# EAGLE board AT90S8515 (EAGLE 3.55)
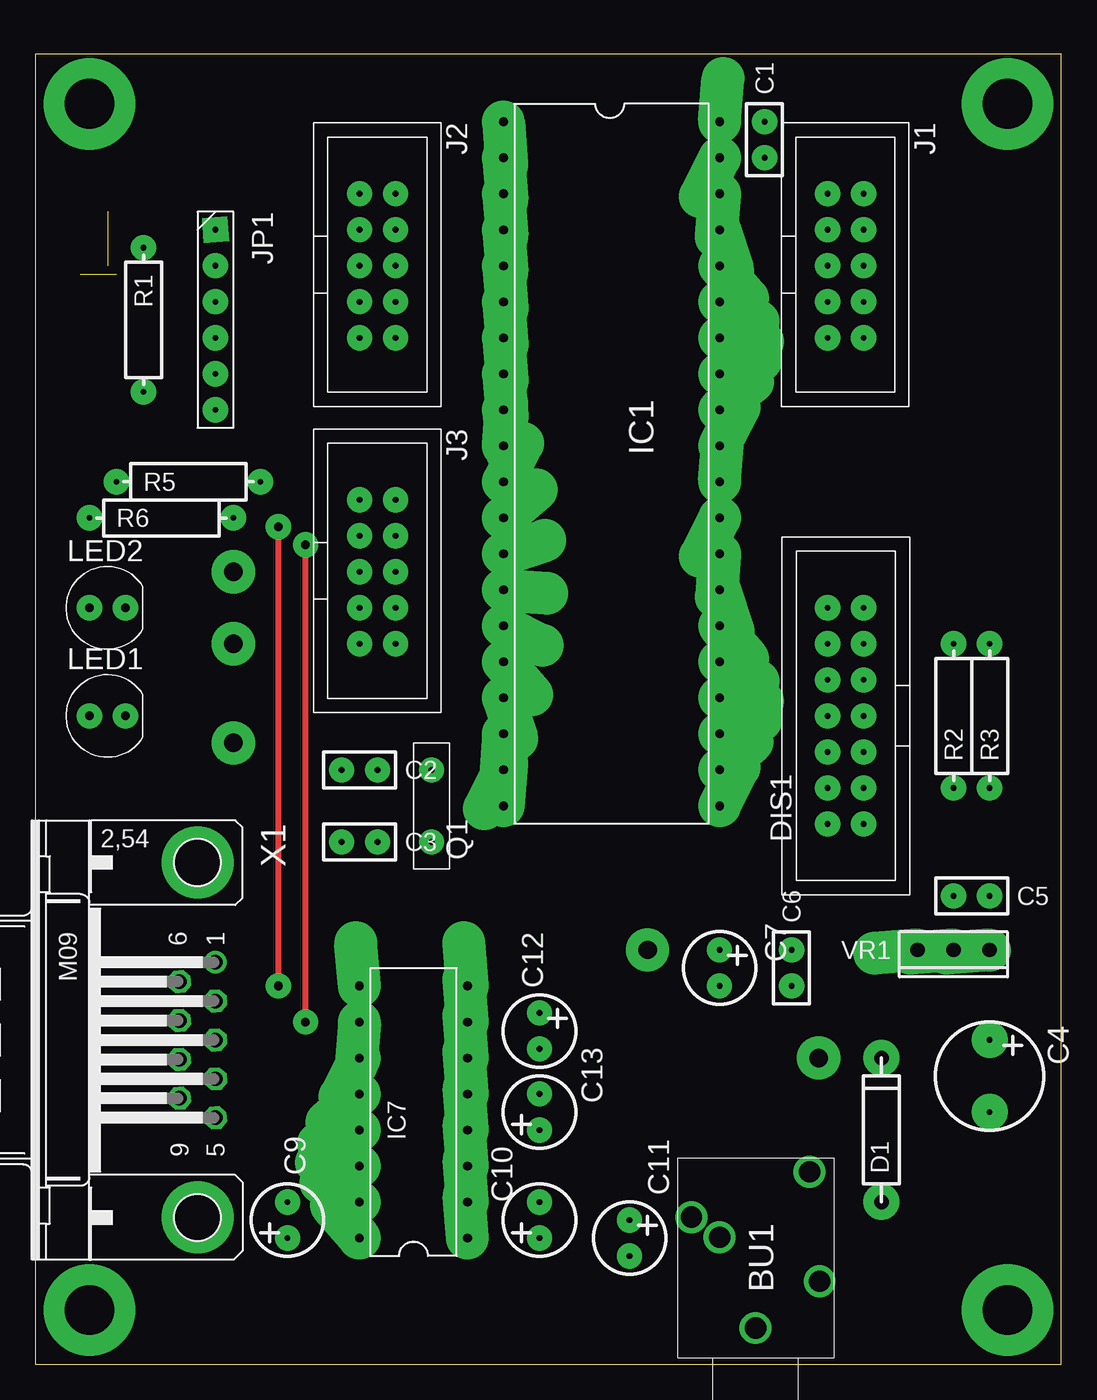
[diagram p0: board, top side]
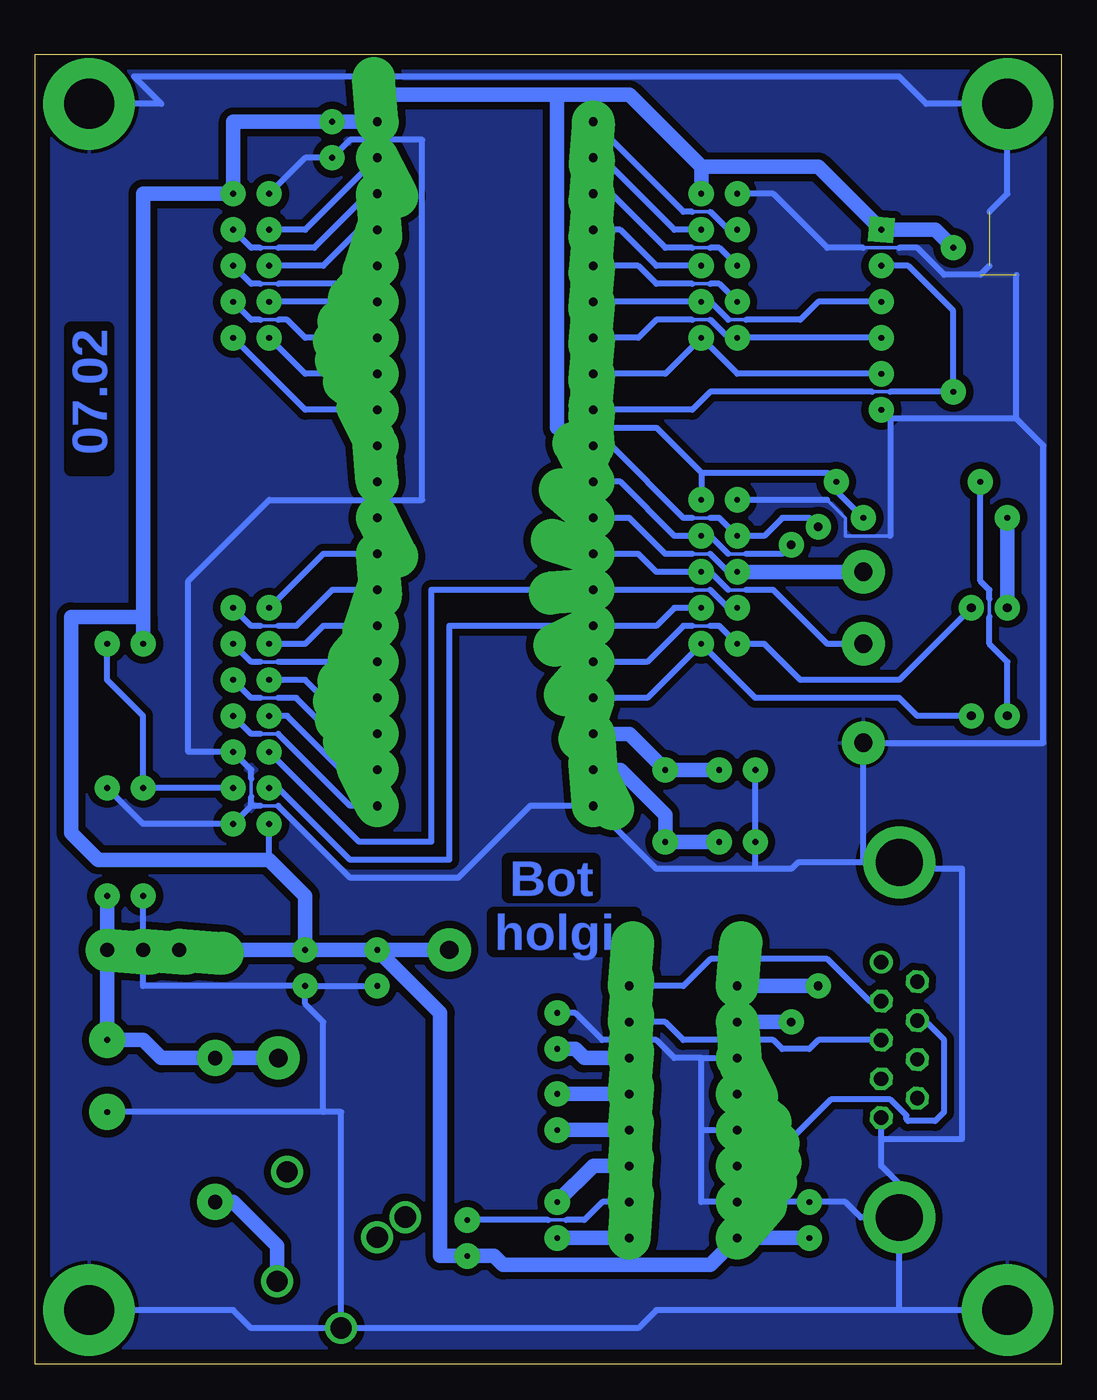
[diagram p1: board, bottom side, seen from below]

Size 72.37 x 92.38 mm. Coordinates in mm from the lower left corner, seen from the top.
Outline: 0,0 72.37,0 72.37,92.38 0,92.38 0,0
Copper layers used: Top, Bottom

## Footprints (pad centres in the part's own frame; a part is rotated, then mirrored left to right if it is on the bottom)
_3,5MM = drill 1.499 pad 2.184 round:  0,0;  3.302,-4.521;  7.823,4.521;  6.401,2.54;  11.024,-3.81
RM2,5 = drill 0.406 pad 1.778 round:  -1.27,0;  1.27,0
KO02 = drill 0.406 pad 2.54 round:  -2.54,0;  2.54,0
KO01 = drill 0.406 pad 1.778 round:  -1.27,0;  1.27,0
O_1A = drill 1.016 pad 2.54 round:  -5.08,0;  5.08,0
7 = drill 0.406 pad 1.778 round:  0,0;  2.54,0;  5.08,0;  7.62,0;  10.16,0;  10.16,2.54;  7.62,2.54;  5.08,2.54;  2.54,2.54;  0,2.54;  12.7,0;  12.7,2.54;  15.24,0;  15.24,2.54
L-40B = drill 0.61 pad 3.048 offset:  -24.13,-7.62;  -21.59,-7.62;  -8.89,-7.62;  -6.35,-7.62;  -19.05,-7.62;  -16.51,-7.62;  -11.43,-7.62;  -13.97,-7.62;  -3.81,-7.62;  -1.27,-7.62;  1.27,-7.62;  3.81,-7.62;  6.35,-7.62;  8.89,-7.62;  11.43,-7.62;  13.97,-7.62;  16.51,-7.62;  19.05,-7.62;  21.59,-7.62;  24.13,-7.62;  24.13,7.62;  21.59,7.62;  19.05,7.62;  16.51,7.62;  13.97,7.62;  11.43,7.62;  8.89,7.62;  6.35,7.62;  3.81,7.62;  1.27,7.62;  -1.27,7.62;  -3.81,7.62;  -6.35,7.62;  -8.89,7.62;  -11.43,7.62;  -13.97,7.62;  -16.51,7.62;  -19.05,7.62;  -21.59,7.62;  -24.13,7.62
L-16B = drill 0.61 pad 3.048 offset:  -8.89,-3.81;  -6.35,-3.81;  6.35,-3.81;  8.89,-3.81;  -3.81,-3.81;  -1.27,-3.81;  3.81,-3.81;  1.27,-3.81;  8.89,3.81;  6.35,3.81;  3.81,3.81;  1.27,3.81;  -1.27,3.81;  -3.81,3.81;  -6.35,3.81;  -8.89,3.81
5 = drill 0.406 pad 1.778 round:  0,0;  2.54,0;  5.08,0;  7.62,0;  10.16,0;  10.16,2.54;  7.62,2.54;  5.08,2.54;  2.54,2.54;  0,2.54
6 = drill 0.406 pad 1.778 square:  0,0 | drill 0.406 pad 1.778 round:  5.08,0;  10.16,0;  12.7,0;  7.62,0;  2.54,0
D_5MM = drill 0.61 pad 1.778 round:  -1.27,0;  1.27,0
GEL = drill 1.295 pad 3.048 round:  0,0
ARZ_ST = drill 0.406 pad 1.778 round:  -2.54,0;  2.54,0
S04 = drill 0.406 pad 1.778 round:  -5.08,0;  5.08,0
HRUNG = drill 3.505 pad 6.452 round:  0,0
220A = drill 1.016 pad 3.048 offset:  -2.54,0;  0,0;  2.54,0
9HP = drill 1.016 pad 1.6 octagon:  5.486,1.27;  2.743,1.27;  0,1.27;  -2.743,1.27;  4.115,-1.27;  1.372,-1.27;  -1.372,-1.27;  -4.115,-1.27 | drill 1.016 pad 1.6 round:  -5.486,1.27 | drill 3.302 pad 5.08 round:  -12.522,0;  12.522,0

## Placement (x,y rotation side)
BU1  BU_3,5MM  [_3,5MM]  50.8,2.54 90 top
C1  C100NK  [RM2,5]  51.44,86.36 90 top
C2  22p  [RM2,5]  22.86,41.91 0 top
C3  22p  [RM2,5]  22.86,36.83 0 top
C4  470u/25  [KO02]  67.31,20.32 270 top
C5  C100NK  [RM2,5]  66.04,33.02 0 top
C6  C100NK  [RM2,5]  53.34,27.94 90 top
C7  100u  [KO01]  48.26,27.94 270 top
C9  10u  [KO01]  17.78,10.16 90 top
C10  10u  [KO01]  35.56,10.16 90 top
C11  10u  [KO01]  41.91,8.89 270 top
C12  10u  [KO01]  35.56,23.5 270 top
C13  10u  [KO01]  35.56,17.78 90 top
D1  1N4001  [O_1A]  59.69,16.51 90 top
DIS1  LCD1  [7]  58.42,38.1 90 top
IC1  90S8515-P  [L-40B]  40.64,63.5 270 top
IC7  MAX232  [L-16B]  26.67,17.78 90 top
J1  8BITPORT  [5]  55.88,82.55 270 top
J2  8BITPORT  [5]  22.86,82.55 270 top
J3  8BITPORT  [5]  22.86,60.96 270 top
JP1  PINHD-1X6  [6]  12.7,80.01 270 top
LED1  rot  [D_5MM]  5.08,45.72 0 top
LED2  grn  [D_5MM]  5.08,53.34 0 top
N1  Int1  [GEL]  13.97,50.8 0 top
N2  Int0  [GEL]  13.97,55.88 0 top
N3  gnd  [GEL]  13.97,43.81 0 top
N4  +5V  [GEL]  43.18,29.21 0 top
N5  +Ub  [GEL]  55.24,21.59 0 top
Q1  8MHz  [ARZ_ST]  27.94,39.37 90 top
R1  100k  [S04]  7.62,73.66 270 top
R2  12k  [S04]  64.77,45.72 90 top
R3  1k  [S04]  67.31,45.72 90 top
R5  1k  [S04]  10.79,62.23 0 top
R6  1k  [S04]  8.89,59.69 0 top
U$30  BOHRUNG  [HRUNG]  3.81,88.9 0 top
U$31  BOHRUNG  [HRUNG]  68.58,88.9 0 top
U$32  BOHRUNG  [HRUNG]  68.58,3.81 0 top
U$33  BOHRUNG  [HRUNG]  3.81,3.81 0 top
VR1  7805  [220A]  64.77,29.21 180 top
X1  M09HP  [9HP]  11.43,22.86 270 top

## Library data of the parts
BU1 = bts
C1-C7 C9-C13 D1 DIS1 IC1 IC7 J1-J3 JP1 LED1 LED2 Q1 R1-R3 R5 R6 VR1 = holg_plt
N1-N5 U$30-U$33 = holgnorm
X1 = subd-a

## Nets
+5V: C1. C6. C7. C9. C11. DIS1. IC1. IC7. J1. J2. J3. JP1. N4. R1. R2. R5. R6. VR1.
GND: BU1. C1. C2. C3. C4. C5. C6. C7. C9. C12. DIS1. IC1. IC7. J1. J2. J3. JP1. N3. R3. U$30. U$31. U$32. U$33. VR1. X1.
INT0: IC1. J3. N2.
INT1: IC1. J3. N1.
LCD_CS: DIS1. IC1. J3.
LCD_RS: DIS1. IC1. J3.
MISO: IC1. J2. JP1.
MOSI: IC1. J2. JP1.
N$1: DIS1. IC1.
N$2: DIS1. IC1.
N$3: DIS1. IC1.
N$4: DIS1. IC1.
N$5: DIS1. IC1.
N$6: C3. IC1. Q1.
N$7: DIS1. IC1.
N$8: C2. IC1. Q1.
N$9: C12. IC7.
N$10: C11. IC7.
N$11: DIS1. IC1.
N$12: C10. IC7.
N$13: C13. IC7.
N$14: IC1. J1.
N$15: C10. IC7.
N$16: DIS1. IC1.
N$17: C13. IC7.
N$18: IC1. J1.
N$19: IC1. J1.
N$20: DIS1. R2. R3.
N$21: IC1. J1.
N$22: IC1. J1.
N$23: IC1. J1.
N$25: IC1. J1.
N$26: IC1. J1.
N$29: IC1. J3. LED1.
N$30: IC1. J2.
N$31: IC1. J2.
N$32: IC1. J2.
N$33: IC1. J2.
N$34: IC1. J2.
N$35: IC1. J3. LED2.
N$36: LED1. R5.
N$37: LED2. R6.
N$42: C4. C5. D1. N5. VR1.
N$50: BU1. D1.
RESET: IC1. JP1. R1.
RTS_OUT: IC7. X1.
RXD: IC1. IC7. J3.
RXD_IN: IC7. X1.
SCK: IC1. J2. JP1.
TXD: IC1. IC7. J3.
TXD_OUT: IC7. X1.

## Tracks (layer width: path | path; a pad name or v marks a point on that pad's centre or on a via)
+5V
  Bottom 0.406: R6. 15.88,61.59 R5. 16.51,62.87 25.4,62.87 | 25.4,62.87 J3. | 25.4,62.87 28.57,66.04 35.56,66.04 | 55.88,35.56 55.88,38.1
  Bottom 1.016: 17.78,8.89 IC7. 24.77,6.99 39.37,6.99 40.01,7.62 C11. 43.81,7.62 43.81,24.77 48.26,29.21 | C6. VR1. | 48.26,29.21 C6. | 7.62,78.74 8.89,80.01 12.7,80.01 17.14,84.45 25.4,84.45 | 35.56,89.53 35.56,66.04 | 25.4,84.45 J2. | 25.4,84.45 30.48,89.53 35.56,89.53 | 35.56,89.53 48.26,89.53 IC1. C1. 58.42,87.63 J1. 64.77,82.55 64.77,52.7 | C6. 53.34,33.02 55.88,35.56 67.94,35.56 69.85,37.47 69.85,52.7 64.77,52.7 | 64.77,52.7 R2. | 48.26,29.21 N4.
GND  (2 unrouted)
  Bottom 0.254: 16.51,60.96 15.24,59.69 15.24,58.42 12.06,58.42 | 57.15,40.01 57.15,41.27 | 55.24,39.37 56.52,39.37 | 11.43,78.74 13.97,78.74
  Bottom 0.406: X1. 11.43,12.7 12.7,13.97 12.7,15.88 | 12.7,15.88 12.7,17.37 | 12.7,15.88 6.99,15.88 6.99,34.92 8.89,34.92 9.35,35.38 11.43,35.38 13.79,35.38 | 13.79,35.38 13.97,35.56 N3. 1.27,43.81 1.27,64.77 3.17,66.67 | X1. 14.15,10.34 15.24,11.43 C9. 22.86,11.43 25.4,11.43 25.4,16.51 | 25.4,16.51 22.86,16.51 | 25.4,16.51 25.4,21.59 | 25.4,21.59 22.86,21.59 | 25.4,21.59 27.3,21.59 28.57,22.86 32.38,22.86 34.29,24.77 35.56,24.77 | 11.43,3.81 X1. | U$33. 11.43,3.81 | 50.8,2.54 29.84,2.54 28.57,3.81 11.43,3.81 | 67.31,40.64 64.77,38.1 58.42,38.1 57.15,39.37 | 64.77,33.02 64.77,29.21 64.77,26.67 53.34,26.67 | 53.34,26.67 C7. | U$32. 58.42,3.81 57.15,2.54 50.8,2.54 | 52.07,17.78 50.8,17.78 50.8,2.54 | 52.07,17.78 C4. | 52.07,17.78 52.07,24.13 53.34,25.4 53.34,26.67 | 21.59,41.91 21.59,36.83 21.59,34.92 | 21.59,34.92 28.57,34.92 33.02,39.37 37.47,39.37 42.55,34.29 50.16,34.29 55.24,39.37 | 5.08,77.47 5.71,76.83 8.26,76.83 10.16,78.74 11.43,78.74 | 22.86,82.55 20.32,82.55 16.51,78.74 13.97,78.74 | 16.51,60.96 22.86,60.96 | 12.06,66.67 12.06,58.42 | 12.06,66.67 12.7,67.31 | 3.17,66.67 12.06,66.67 | 3.17,66.67 3.17,76.83 | 5.08,81.28 3.81,82.55 U$30. 9.53,88.9 11.43,90.81 65.41,90.81 63.5,88.9 U$31. | 13.79,35.38 18.59,35.38 19.05,34.92 21.59,34.92 | 55.88,82.55 53.34,85.09 51.44,85.09 50.16,86.36 45.09,86.36 45.09,60.96 55.88,60.96 61.59,55.24 61.59,43.18 58.42,43.18 57.15,41.91 57.15,41.27 | 57.15,39.37 57.15,40.01 | 56.52,39.37 57.15,39.37
  pour Bottom (isolate 0.508): 0.64,91.44 0.64,0.64 71.75,0.64 71.75,91.44
INT0
  Bottom 0.254: 24.77,57.15 26.04,57.15
  Bottom 0.406: 33.02,59.69 30.48,59.69 27.94,57.15 26.04,57.15 | 24.77,57.15 23.5,55.88 22.86,55.88
  Bottom 1.016: N2. 22.86,55.88
INT1
  Bottom 0.254: 22.23,54.61 23.5,54.61
  Bottom 0.406: 33.02,57.15 29.84,57.15 28.57,55.88 25.4,55.88 24.77,55.88 23.5,54.61 | N1. 16.51,50.8 20.32,54.61 22.23,54.61
LCD_CS
  Bottom 0.254: 24.77,54.61 26.04,54.61
  Bottom 0.406: 55.88,43.18 49.53,36.83 44.45,36.83 44.45,54.61 33.02,54.61 26.04,54.61 | 24.77,54.61 23.5,53.34 22.86,53.34
LCD_RS
  Bottom 0.406: 55.88,40.64 55.24,40.64 50.16,35.56 43.18,35.56 43.18,52.07 33.02,52.07 28.57,52.07 27.3,53.34 25.4,53.34
MISO
  Bottom 0.254: 24.77,73.66 26.04,73.66
  Bottom 0.406: 33.02,72.39 29.84,72.39 28.57,73.66 26.04,73.66 | 24.77,73.66 23.5,72.39 22.86,72.39 12.7,72.39
MOSI
  Bottom 0.254: 22.23,73.66 23.5,73.66
  Bottom 0.406: 33.02,74.93 25.4,74.93 24.77,74.93 23.5,73.66 | 12.7,74.93 17.14,74.93 18.41,73.66 22.23,73.66
N$1
  Bottom 0.254: 55.24,44.45 56.52,44.45
  Bottom 0.406: 48.26,39.37 50.16,39.37 55.24,44.45 | 58.42,45.72 57.15,44.45 56.52,44.45
N$2
  Bottom 0.406: 48.26,41.91 50.8,41.91 54.61,45.72 55.88,45.72
N$3
  Bottom 0.254: 55.24,46.99 56.52,46.99
  Bottom 0.406: 48.26,44.45 51.44,44.45 53.98,46.99 55.24,46.99 | 58.42,48.26 57.15,46.99 56.52,46.99
N$4
  Bottom 0.406: 48.26,46.99 52.07,46.99 53.34,48.26 55.88,48.26
N$5
  Bottom 0.254: 55.24,49.53 56.52,49.53
  Bottom 0.406: 58.42,50.8 57.15,49.53 56.52,49.53 | 48.26,49.53 55.24,49.53
N$6
  Bottom 1.016: C3. 27.94,36.83 27.94,38.73 31.11,41.91 33.02,41.91
N$7
  Bottom 0.406: 48.26,52.07 52.07,52.07 53.34,50.8 55.88,50.8
N$8
  Bottom 1.016: 33.02,44.45 30.48,44.45 Q1. C2.
N$9
  Bottom 1.016: 30.48,21.59 33.66,21.59 34.29,22.23 C12.
N$10
  Bottom 0.254: 34.92,10.16 36.2,10.16
  Bottom 0.406: 30.48,11.43 32.38,11.43 33.66,10.16 34.92,10.16 | 36.2,10.16 41.91,10.16
N$11
  Bottom 0.254: 55.24,52.07 56.52,52.07
  Bottom 0.406: 48.26,54.61 51.44,54.61 53.98,52.07 55.24,52.07 | 58.42,53.34 57.15,52.07 56.52,52.07
N$12
  Bottom 1.016: 30.48,13.97 33.02,13.97 C10.
N$13
  Bottom 1.016: 30.48,19.05 C13.
N$14
  Bottom 0.406: 48.26,85.09 53.34,80.01 55.88,80.01
N$15
  Bottom 1.016: 30.48,8.89 35.56,8.89
N$16
  Bottom 0.406: 48.26,57.15 52.07,57.15 DIS1.
N$17
  Bottom 1.016: 30.48,16.51 35.56,16.51
N$18
  Bottom 0.254: 55.24,78.74 56.52,78.74
  Bottom 0.406: 48.26,82.55 48.9,82.55 52.7,78.74 55.24,78.74 | 58.42,80.01 57.15,78.74 56.52,78.74
N$19
  Bottom 0.406: 48.26,80.01 49.53,80.01 52.07,77.47 55.88,77.47
N$20
  Bottom 0.406: 58.42,40.64 64.77,40.64 64.77,45.72 67.31,48.26 R3.
N$21
  Bottom 0.254: 55.24,76.2 56.52,76.2
  Bottom 0.406: 48.26,77.47 49.53,77.47 50.8,76.2 55.24,76.2 | 58.42,77.47 57.15,76.2 56.52,76.2
N$22
  Bottom 0.406: 48.26,74.93 55.88,74.93
N$23
  Bottom 0.254: 55.24,73.66 56.52,73.66
  Bottom 0.406: 48.26,72.39 53.34,72.39 54.61,73.66 55.24,73.66 | 58.42,74.93 57.15,73.66 56.52,73.66
N$25
  Bottom 0.406: 48.26,69.85 53.34,69.85 55.88,72.39
N$26
  Bottom 0.406: 48.26,67.31 53.34,67.31 58.42,72.39
N$29
  Bottom 0.406: 33.02,46.99 29.21,46.99 25.4,50.8 21.59,46.99 11.43,46.99 10.16,45.72 LED1.
N$30
  Bottom 0.254: 24.77,76.2 26.04,76.2
  Bottom 0.406: 33.02,77.47 29.84,77.47 28.57,76.2 26.04,76.2 | 22.86,74.93 24.13,76.2 24.77,76.2
N$31
  Bottom 0.406: 33.02,80.01 31.11,80.01 28.57,77.47 25.4,77.47
N$32
  Bottom 0.254: 24.77,78.74 26.04,78.74
  Bottom 0.406: 33.02,82.55 31.75,82.55 27.94,78.74 26.04,78.74 | 22.86,77.47 24.13,78.74 24.77,78.74
N$33
  Bottom 0.406: 33.02,85.09 32.38,85.09 27.3,80.01 25.4,80.01
N$34
  Bottom 0.254: 24.77,81.28 26.04,81.28
  Bottom 0.406: 33.02,87.63 26.67,81.28 26.04,81.28 | 24.77,81.28 23.5,80.01 22.86,80.01
N$35
  Bottom 0.254: 24.77,52.07 26.04,52.07
  Bottom 0.406: 33.02,49.53 29.21,49.53 26.67,52.07 26.04,52.07 | LED2. 11.43,48.26 18.41,48.26 20.95,50.8 22.86,50.8 24.13,52.07 24.77,52.07
N$36
  Bottom 0.254: 5.08,52.7 5.08,53.98
  Bottom 0.406: 5.71,62.23 5.71,55.24 5.08,54.61 5.08,53.98 | 3.81,45.72 3.81,49.53 5.08,50.8 5.08,52.7
N$37
  Bottom 1.016: 3.81,53.34 3.81,59.69
N$42
  Bottom 1.016: C5. 67.31,29.21 67.31,22.86 64.77,22.86 63.5,21.59 D1. N5.
N$50
  Bottom 1.016: 55.32,5.84 55.32,8.33 58.42,11.43 59.69,11.43
RESET
  Bottom 0.254: 12.06,68.58 13.34,68.58
  Bottom 0.406: 33.02,67.31 26.04,67.31 24.77,68.58 13.34,68.58 | JP1. 10.79,77.47 7.62,74.3 R1. 12.06,68.58
RTS_OUT
  Bottom 0.406: 10.16,24.23 9.63,24.23 8.26,22.86 8.26,17.78 8.89,17.14 10.79,17.14 10.92,17.27 10.92,17.53 12.06,18.67 16.26,18.67 20.95,13.97 22.86,13.97
RXD  (via drill 0.61 pad 1.78)
  Top 0.406: v17.14,26.67 v17.14,59.05
  Bottom 0.254: 24.77,59.69 26.04,59.69
  Bottom 0.406: 33.02,64.77 31.75,64.77 26.67,59.69 26.04,59.69 | v17.14,59.05 17.78,59.69 19.68,59.69 20.95,58.42 22.86,58.42 24.13,59.69 24.77,59.69
  Bottom 1.016: v17.14,26.67 22.86,26.67
RXD_IN
  Bottom 0.406: 12.7,25.6 13.54,25.6 16.51,28.57 24.77,28.57 26.67,26.67 30.48,26.67
SCK
  Bottom 0.406: 33.02,69.85 27.94,69.85 25.4,72.39 22.86,69.85 12.7,69.85
TXD  (via drill 0.61 pad 1.78)
  Top 0.406: v19.05,24.13 v19.05,57.78
  Bottom 0.254: 22.23,57.15 23.5,57.15
  Bottom 0.406: 33.02,62.23 31.11,62.23 27.3,58.42 25.4,58.42 24.77,58.42 23.5,57.15 | v19.05,57.78 19.68,57.15 22.23,57.15
  Bottom 1.016: v19.05,24.13 22.86,24.13
TXD_OUT
  Bottom 0.406: 30.48,24.13 27.94,24.13 26.67,22.86 20.32,22.86 19.68,22.23 17.78,22.23 17.14,22.86 12.7,22.86

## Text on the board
Bottom: 07.02 | Bot | holgi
